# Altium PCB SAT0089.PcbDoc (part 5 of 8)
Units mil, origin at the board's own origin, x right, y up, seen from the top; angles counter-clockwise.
Board outline 4075 x 2715 mil, 6 copper layers (Top Layer, InternalPlane1, MidLayer1, Internal Plane 3, InternalPlane2, Bottom Layer), stack 67.4 mil thick; 538 components, 405 nets, 1716 pads, 1236 vias.
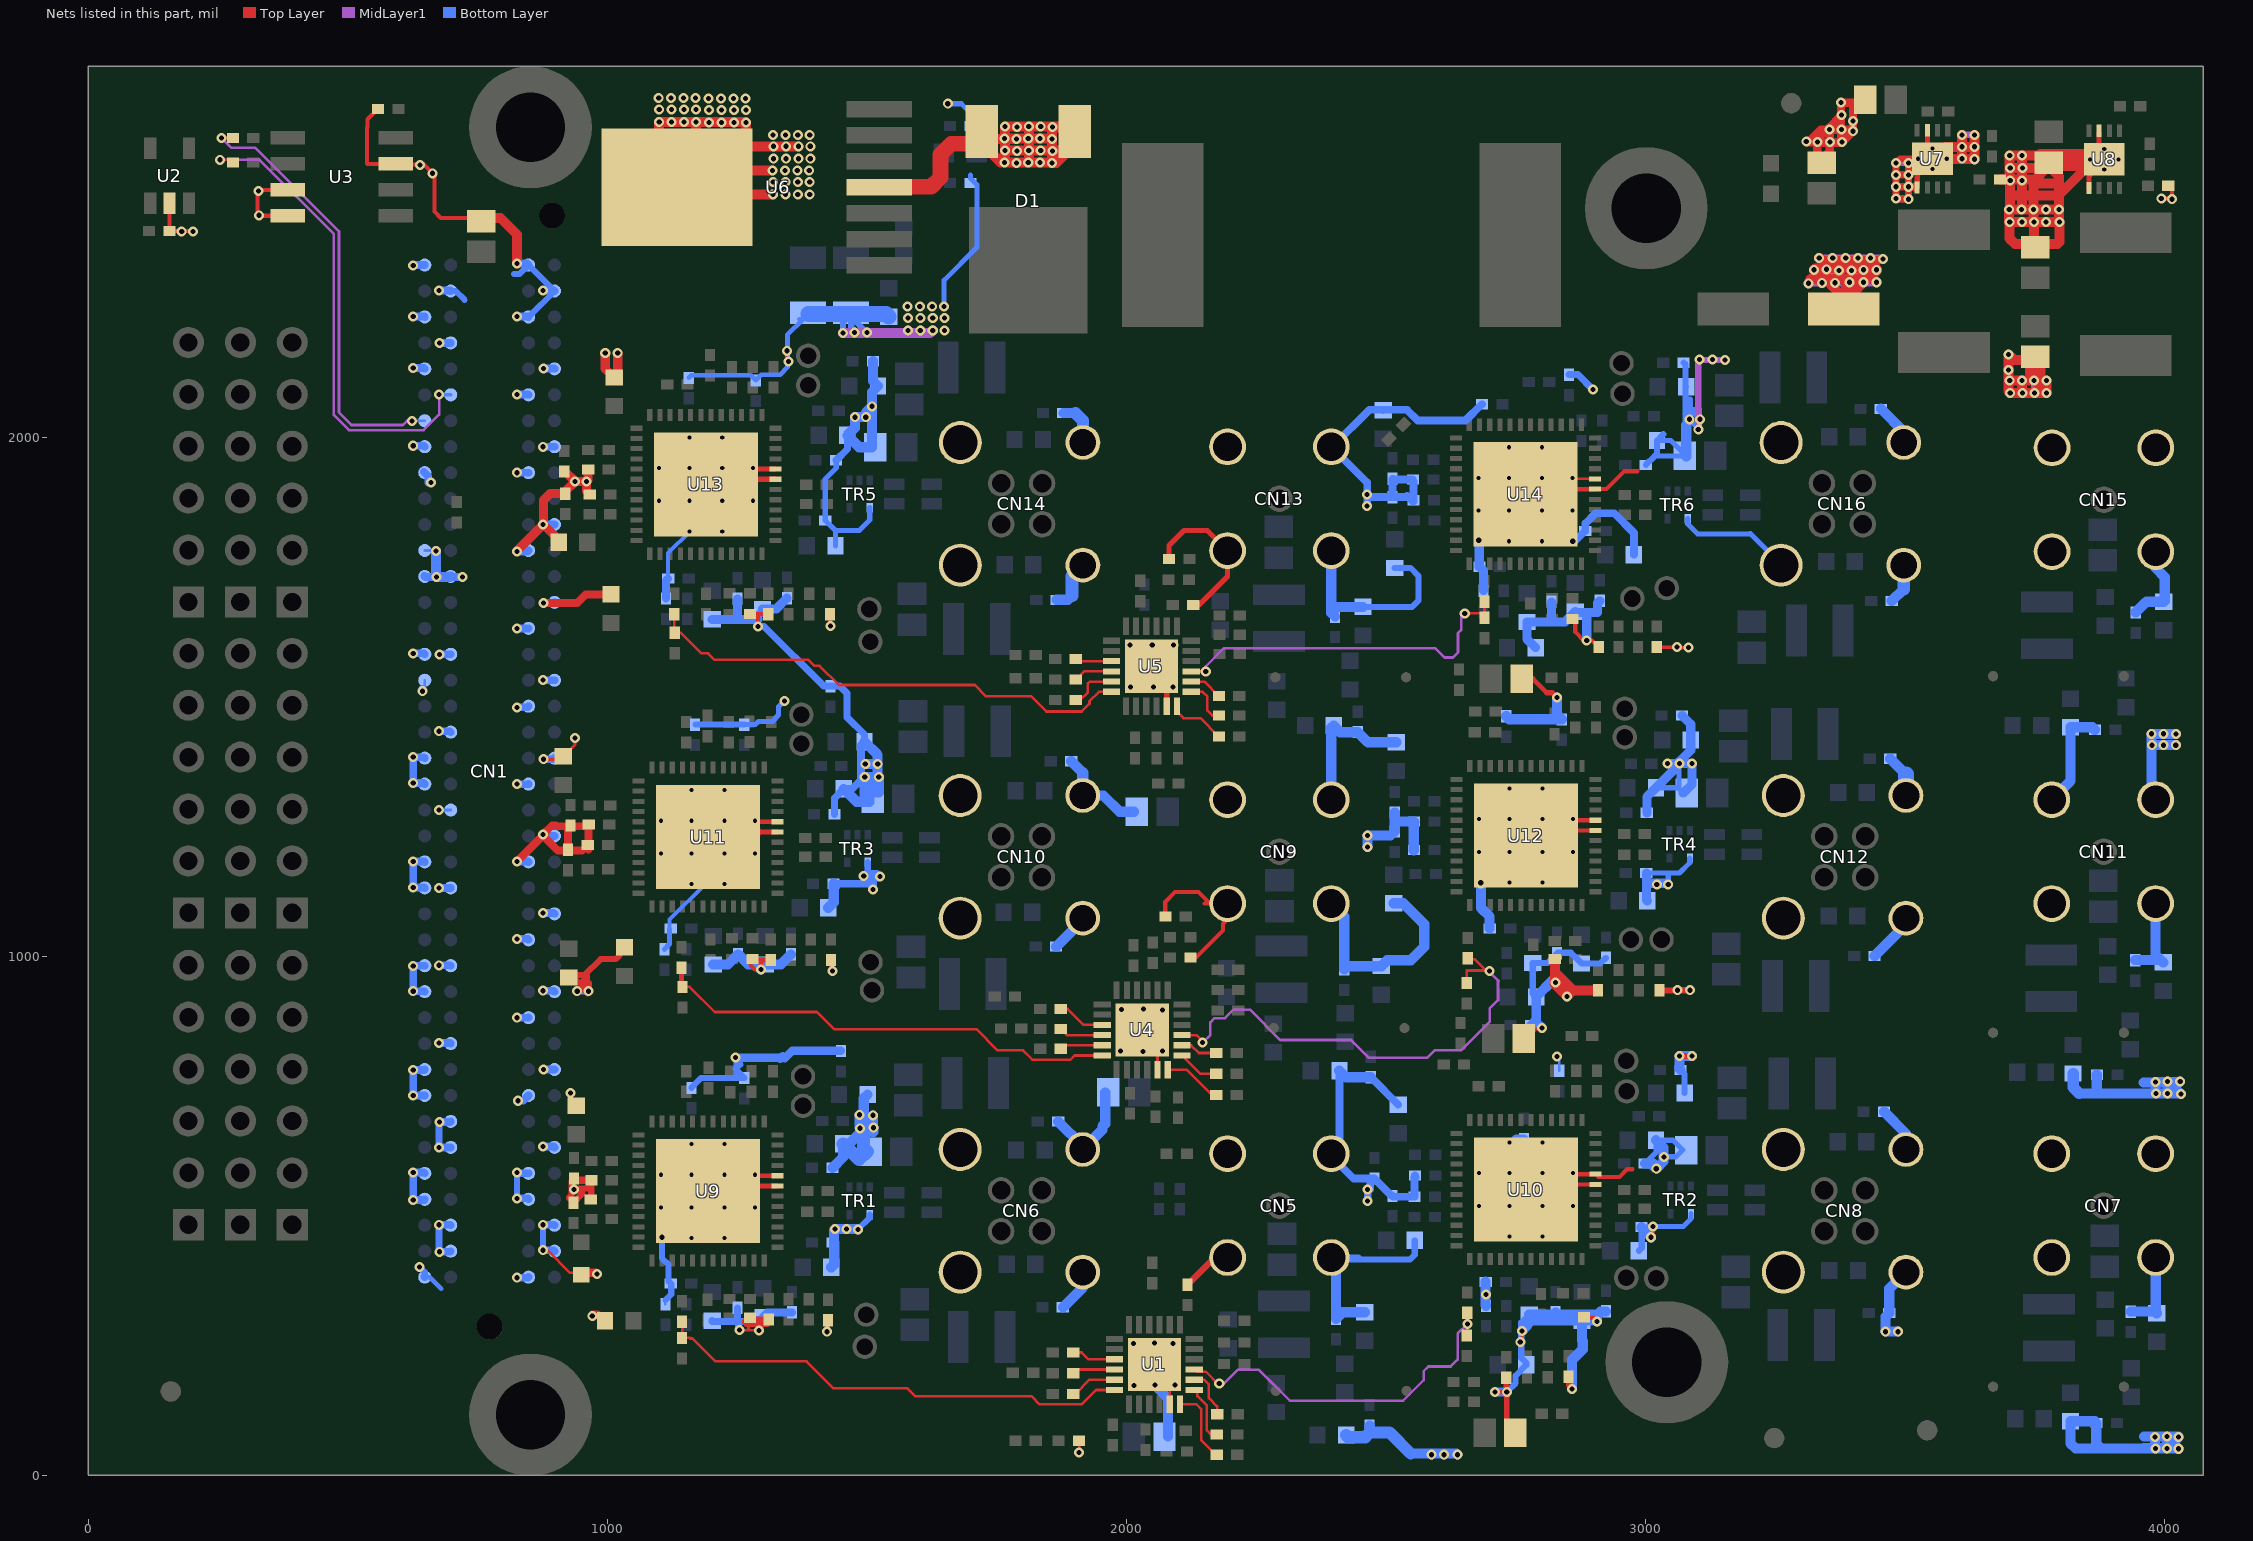
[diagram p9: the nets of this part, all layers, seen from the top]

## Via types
v1: diameter 19.29, hole 9.84, Top Layer to Bottom Layer, tented both sides, 1155 vias
v2: diameter 19.68, hole 7.87, Top Layer to Bottom Layer, tented both sides, 80 vias
v3: diameter 22, hole 10, Top Layer to Bottom Layer, tented both sides, 1 vias

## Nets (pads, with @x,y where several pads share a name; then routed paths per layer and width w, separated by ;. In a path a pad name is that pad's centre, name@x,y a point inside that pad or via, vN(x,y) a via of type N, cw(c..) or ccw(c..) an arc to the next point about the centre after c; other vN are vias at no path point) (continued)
DGND: C1.2 C2.1 C3.2 C4.2 C5.1 C6.1 C7.2 C8.2 C9.2 C11.2 C12.2 C13.2 C14.2 C15.2 C16.2 C17.2 C18.2 C19.2 C22.2 C27.2 C28.2 C29.2 C30.2 C31.2 C32.2 C33.2 C34.2 C35.2 C36.2 C37.2 C38.2 C39.2 C40.2 C41.2 C42.2 C43.2 C44.2 C45.2 C46.2 C47.2 C48.2 C49.2 C50.2 C51.2 C54.2 C59.2 C60.2 C61.2 C62.2 C63.2 C64.2 C65.2 C66.2 C67.2 C68.2 C69.2 C70.2 C71.2 C72.2 C73.2 C74.2 C75.2 C76.2 C77.2 C78.2 C79.2 C80.2 C81.2 C82.2 C83.2 C86.2 C91.2 C92.2 C93.2 C94.2 C95.2 C96.2 C97.2 C98.2 C99.2 C100.2 C101.2 C102.2 C103.2 C104.2 C105.2 C106.2 C107.2 C108.2 C109.2 C110.2 C111.2 C112.2 C113.2 C114.2 C115.2 C118.2 C123.2 C124.2 C125.2 C126.2 C127.2 C128.2 C129.2 C130.2 C131.2 C132.2 C133.2 C134.2 C135.2 C136.2 C137.2 C138.2 C139.2 C140.2 C141.2 C142.2 C143.2 C144.2 C145.2 C146.2 C147.2 C150.2 C155.2 C156.2 C157.2 C158.2 C159.2 C160.2 C161.2 C162.2 C163.2 C164.2 C165.2 C166.2 C167.2 C168.2 C169.2 C170.2 C171.2 C172.2 C173.2 C174.2 C175.2 C176.2 C177.2 C178.2 C179.2 C182.2 C186.2 C187.2 C188.2 C189.2 C190.2 C191.2 C192.2 C193.2 C194.2 C195.2 C196.2 C197.2 C198.2 C199.2 C200.2 C201.2 C202.2 C203.2 C204.2 C205.2 C206.2 C208.2 C209.2 C210.2 C211.2 C212.2 C213.2 CN1.1 CN1.4 CN1.5 CN1.8 CN1.9 CN1.12 CN1.13 CN1.16 CN1.17 CN1.20 CN1.21 CN1.24 CN1.25 CN1.28 CN1.29 CN1.32 CN1.33 CN1.36 CN1.38 CN1.40 CN1.42 CN1.43 CN1.46 CN1.47 CN1.50 CN1.53 CN1.56 CN1.59 CN1.62 CN1.65 CN1.68 CN1.77 CN1.79 CN1.81 CN1.84 CN1.85 CN1.88 CN1.91 CN1.94 CN1.97 CN1.100 CN1.103 CN1.106 CN1.109 CN1.112 CN1.115 CN1.118 CN1.120 CN1.122 CN1.123 CN1.126 CN1.129 CN1.132 CN1.135 CN1.138 CN1.141 CN1.144 CN1.147 CN1.150 CN1.153 CN1.156 CN1.159 CN5.2 CN5.3 CN5.4 CN5.5 CN6.5 CN6.6 CN6.7 CN6.8 CN7.2 CN7.3 CN7.4 CN7.5 CN8.5 CN8.6 CN8.7 CN8.8 CN9.2 CN9.3 CN9.4 CN9.5 CN10.5 CN10.6 CN10.7 CN10.8 CN11.2 CN11.3 CN11.4 CN11.5 CN12.5 CN12.6 CN12.7 CN12.8 CN13.2 CN13.3 CN13.4 CN13.5 CN14.5 CN14.6 CN14.7 CN14.8 CN15.2 CN15.3 CN15.4 CN15.5 CN16.5 CN16.6 CN16.7 CN16.8 D1.1 D1.3 R3.2 R8.2 R11.2 R13.1 R15.2 R16.2 R19.2 R21.2 R28.1 R29.1 R30.2 R38.2 R39.2 R55.1 R56.1 R57.2 R63.2 R64.2 R79.1 R80.1 R81.2 R87.2 R88.2 R103.1 R104.1 R105.2 R111.2 R112.2 R127.1 R128.1 R129.2 R135.2 R136.2 R151.1 R152.1 R153.2 R159.2 R160.2 TR1.4 TR2.4 TR3.4 TR4.4 TR5.4 TR6.4 U1.23 U1.25 U2.2 U3.3 U3.4 U3.7 U4.23 U4.25 U5.23 U5.25 U6.4 U6.8 U7.1 U7.7 U7.9 U8.1 U8.7 U8.9 U9.43 U9.44 U9.49 U10.43 U10.44 U10.49 U11.43 U11.44 U11.49 U12.43 U12.44 U12.49 U13.43 U13.44 U13.49 U14.43 U14.44 U14.49 | length 34902.5
  Top Layer w5: v1(876,434) 885,434 928.5,390.5 C34.2@950,390.5 ; v1(929,737) 929,723.5 C29.2@940,712.5 ; U9.49@1194,548 U9.49@1285,548 ; v1@1251,280 v1(1255,280) 1275,280 ; v1(1292,279) 1291,280 1275,280 ; R39.2@1310,299 1272,299 1272,283 1275,280 ; v1(1346,2167) 1346,2149 v1(1349,2146) ; v1(1909,44) R3.2@1909,67 ; U4.25@2030.55,858.35 U4.25@2032,856.9 ; v1(2032,817) U4.25@2032,856.9 ; U1.25@2054,214 2083.53,184.47 U1.23@2083.53,137.23 ; U4.23@2060.08,781.57 2060.08,828.82 U4.25@2032,856.9 ; U10.49@2736,462 U10.49@2808,462 ; U12.49@2740,1144 2740,1203 U12.49@2770,1233 2770,1188 U12.49@2750,1168 ; U14.49@2749,1825 2769,1845 2769,1890 U14.49@2769,1890.53 2769.53,1890.53 2790.53,1890.53 2800.37,1900.37 U14.49@2820.06,1920.06 ; U10.49@2750,486 U10.49@2770,506 ; v1(2759,257) 2762,260 v1(2762,278) ; U10.49@2770,551 U10.49@2770,506 ; C139.2@2772,842 2792,862 v1(2801,862) ; U14.49@2798,1919.53 2798.53,1920.06 U14.49@2820.06,1920.06 ; U10.49@2809,461 U10.49@2808,462 ; U14.49@2860,1895 U14.49@2865.37,1900.37 ; U14.49@2860,1960 U14.49@2820.06,1920.06 ; U14.44@2902.86,1920.06 2860,1920.06 U14.49@2820.06,1920.06 ; v1(3011,459) 3015,463 v1(3015,480) ; U10.49@2770,506 2770,500 U10.49@2808,462
  Top Layer w6: v1(877,1380) 909.5,1380 938,1408.5 v1(938,1421) ; C92.2@929,1252 C210.2@962,1252
  Top Layer w7: R159.2@3022,1596 v1(3061,1596) 3067,1596 3068,1595 v1(3083,1595)
  Top Layer w7.87: U13.49@1100,1820 U13.49@1189,1820 ; U11.49@1194,1230 U11.49@1203.84,1239.84 ; R30.2@1274,297 1274,296 R30.2@1275,296 ; U13.49@1277,1909 U13.49@1287.37,1919.37 ; U11.49@1290.84,1239.84 U11.49@1203.84,1239.84 ; v1(1292,279) v1@1293,278 ; 1296,296 v1@1296,285 ; R39.2@1307,296 v1@1296,285 ; U11.44@1327.86,1259.53 1223.53,1259.53 U11.49@1203.84,1239.84 ; v1(1423,277) 1425,279 R38.2@1425,299 ; R87.2@1431,993 1431,975 v1(1434,972) ; v1@3723.83,2497.17 v1(3726,2495) ; v1(3994,2460) 4014,2460 v1(4015,2459) 4015,2478 R21.2@4008,2485 ; v1@1293,278 v1@1296,281 ; v1@1293,278 1296,278 v1@1296,281 ; v1@1296,281 v1@1296,285
  Top Layer w8: U2.2@156.54,2452.83 U2.2@156.54,2450.87 156.54,2398.03 156.85,2397.72 v1@180,2397.72 ; v1(180,2397) v1@180,2397.72 ; v1(202,2397) 201.28,2397.72 v1@180,2397.72 ; v1(329,2428) 329.95,2427.05 v1@332.95,2427.05 ; U3.3@385.21,2477.05 329.05,2477.05 326,2474 326,2434 v1@332.95,2427.05 ; C4.2@558,2633 538,2613 538,2598 537,2597 537,2528 537.95,2527.05 593.21,2527.05 594.26,2526 647,2526 667,2506 667,2435 679,2423 C1.2@757,2423 ; U9.49@1203.84,557.84 1223.53,577.53 U9.44@1327.86,577.53 ; R129.2@1274.69,1660 1309,1660 1310,1659 1290,1659 v1(1290,1636) ; R81.2@1276,993 1276,983 1284,975 v1(1296,975) ; R135.2@1429,1659 1429,1638 v1(1430,1637) ; R8.2@2075,1077 2075,1105 2094,1124 2139,1124 CN9.3@2161,1102 ; C5.1@2120.5,997.5 2121,998 C5.1@2123.68,998 2134,998 2186,1050 2186,1063 2195,1072 CN9.3@2195,1102 ; 2151,1102 CN9.3@2161,1102 ; CN9.3@2200,1102 CN9.3@2195,1102 ; U14.49@2769,1890 2769.53,1890.53 U14.49@2778.84,1899.84 ; U10.49@2770,551 U10.49@2779.84,560.84 ; U12.49@2770,1233 U12.49@2779.84,1242.84 ; U14.49@2778.32,1899.84 U14.49@2778.84,1899.84 ; U14.49@2778.84,1900.37 2798,1919.53 2798.53,1919.53 2779.37,1900.37 U14.49@2778.84,1899.84 ; R153.2@2865,1645 2865,1625 2881,1609 v1(2887,1609) 2897,1609 R160.2@2910,1596 ; R57.2@2880,304 2900,304 v1(2907,297) ; U14.43@2902.86,1900.37 2925.37,1900.37 2960,1935 2985,1935 ; U10.43@2903.86,560.84 U10.49@2779.84,560.84 ; U12.43@2903.86,1242.84 U12.49@2779.84,1242.84 ; U12.44@2903.86,1262.53 2799.53,1262.53 U12.49@2779.84,1242.84 ; 2975,590 2965,590 2950,575 2909.39,575 U10.44@2903.86,580.53 2799.53,580.53 U10.49@2779.84,560.84 ; v1@332.95,2427.05 385.21,2427.05 385.17,2427 333,2427 v1@332.95,2427.05 ; CN9.3@2161,1102 CN9.3@2195,1102
  Top Layer w9: U14.49@2769,1890.53 2778.32,1899.84 2778.84,1900.37 2779.37,1900.37 2800.37,1900.37 2860,1900.37 2865.37,1900.37 U14.43@2902.86,1900.37
  Top Layer w9.84: U9.49@1194,548 1203.84,557.84 U9.43@1327.86,557.84 ; U13.49@1199.84,1919.37 1287.37,1919.37 U13.43@1323.86,1919.37 ; U13.49@1219.53,1939.06 U13.44@1323.86,1939.06 ; U11.49@1290.84,1239.84 U11.43@1327.86,1239.84 ; U12.49@2740,1144 2741,1143 U12.49@2809,1143 ; U14.49@2747,1963 U14.49@2810,1963 ; U14.49@2810,1962 U14.49@2810,1963 ; U14.49@2860,1895 2860,1900.37 2860,1920.06 2860,1960 2863,1963 U14.49@2810,1963 ; U7.1@3523.93,2481.43 U7.9@3523.93,2507.02 ; U7.9@3543.61,2546.39 U7.7@3543.61,2591.66 ; U8.1@3854.64,2477.49 3854.64,2503.08 U8.9@3874.56,2523 ; U8.9@3874.32,2542.45 U8.7@3874.32,2587.72
  Top Layer w10: U13.49@1199.84,1919.37 U13.49@1219.53,1939.06 ; R81.2@1276,993 1296,993 ; v1(1296,975) 1296,993 ; R88.2@1315,993 1296,993 ; v1(2050,1600) 2050,1560.87 U5.25@2048.27,1559.13 2077.8,1529.61 U5.23@2077.8,1482.36 ; R11.2@2082,1766 2082,1792 2111,1821 2155.97,1821 CN13.3@2195,1781.97 2195,1732 2140,1677 C6.1@2129,1677 ; v1(2710,161) v1(2733,161) ; R64.2@2732,188 2732,162 v1(2733,161) ; C75.2@2756,82 2756,97 2733,97 v1(2733,161) ; C202.2@2768,1535 2783,1535 2810,1508 2821,1508 v1(2830,1499) ; R63.2@2852,190 2852,174 v1(2859,167)
  Top Layer w11.81: C98.2@926,959.5 930,963.5 C98.2@930,964.5 ; 950,941 952,939 v1@961,930 ; 950,949.5 945,949.5 C98.2@930,964.5 ; 961,963 v1@961,930 ; v1(964,933) 962,931 962,929 v1@961,930 ; C42.2@995.5,298 C42.2@986.5,307 ; C106.2@1023.5,1017.5 1033,1017.5 1033,1012 1016,995 987,995 956.5,964.5 C98.2@930,964.5 ; U13.49@1190,1909.53 U13.49@1199.84,1919.37 ; U7.9@3523.93,2507.02 3553.46,2536.54 U7.9@3543.61,2546.39 ; C42.2@986.5,307 981.5,312 971,312 v1(971,307) C42.2@986.5,307
  Top Layer w12: C28.2@936,570 936,572 931,567 v1@931,551 ; v1(942,933) 946,933 v1@950,937 ; 952,939 v1@950,937 ; 959.5,959 950,949.5 950,941 v1@950,937 ; v1(964,933) 964,949 ; C31.2@969,532 969,553 ; C208.2@969,569 969,553 ; C2.1@2118,368 2170,420 CN5.3@2195,420 ; R111.2@3027.02,934.37 3061.37,934.37 v1(3062,935) v1(3086,935) ; v1(3066,808) v1(3090,808) ; v1@931,551 931,540 926,535 935,526 952,543 946,549 ; v1@931,551 v1(936,551) ; v1(936,551) 944,551 946,553 ; v1(936,551) 934,549 946,549 ; 946,549 948,551 946,553 ; 946,553 969,553
  Top Layer w13.78: U1.25@2054,214 2054,175 v1(2055,174) ; v1(3507,2529) v1(3507,2506) ; 3518,2481 3516,2483 v1(3507,2483) ; U7.9@3553.46,2536.54 3490.54,2536.54 v1(3483,2529) v1(3483,2506) ; v1(3483,2483) v1(3507,2483) ; v1(3483,2483) v1(3483,2506) ; v1(3483,2483) v1(3483,2460) 3506,2460 v1(3507,2459) v1(3507,2483) ; v1(3483,2506) v1(3507,2506) ; v1(3507,2483) v1(3507,2506)
  Top Layer w15: v1(826,1183) v1@876,1233 ; C97.2@924,1206 924,1247 C92.2@928,1251 ; C92.2@929,1252 C92.2@928,1251 ; C28.2@936,572 939,569 C208.2@969,569 ; U11.49@1284,1233 U11.49@1290.84,1239.84 ; v1@876,1233 v1(876,1235) 894,1253 900,1253 902,1251 C92.2@928,1251 ; v1@876,1233 905,1204 951,1204 C96.2@962,1215 ; C92.2@928,1251 961,1251 962,1252 964,1254 C96.2@964,1213 ; C96.2@962,1215 C96.2@964,1213 ; C96.2@962,1215 962,1208 964,1206 C96.2@964,1213
  Top Layer w15.75: v1(877,1681) 942,1681 958.5,1697.5 973.5,1697.5
  Top Layer w16: C34.2@950,390.5 977.5,390.5 v1(980,388) ; 973.5,1697.5 C170.2@1007,1697.5 ; v1(3400,2590) 3400,2589 v1@3379,2568 ; C14.2@3417.06,2650.72 3411.35,2645 3397,2645 ; v1@3314,2569 v1@3331,2569 ; v1@3314,2569 v1@3315,2570 ; v1@3314,2569 3311,2569 v1(3310,2570) v1@3315,2570 ; v1@3315,2570 3338,2593 v1@3350,2593 ; v1@3331,2569 3331,2535.16 3339.16,2535.16 3351.32,2547.32 3355,2547.32 v1@3355,2568 ; v1@3331,2569 v1(3332,2569) ; v1(3332,2569) 3332,2575 v1@3350,2593 ; v1(3332,2569) 3333,2568 v1@3355,2568 ; v1@3350,2593 v1@3352.5,2595.5 ; v1@3350,2593 v1(3355,2593) ; v1@3352.5,2595.5 v1@3377,2620 ; v1@3352.5,2595.5 v1(3355,2593) ; v1@3355,2568 v1@3355,2569 ; v1@3355,2568 v1@3356,2568 ; v1@3355,2569 v1(3355,2593) ; v1@3355,2569 v1(3356,2569) ; v1(3355,2593) v1@3377,2593 ; v1@3356,2568 v1@3357,2568 ; v1@3356,2568 v1(3356,2569) ; v1(3356,2569) v1@3357,2568 ; v1@3357,2568 v1@3379,2568 ; v1@3377,2593 3377,2571 v1(3379,2569) v1@3379,2568 ; v1@3377,2593 v1@3377,2620 ; v1@3377,2593 v1(3378,2593) 3399,2593 3400,2594 v1(3400,2610) 3400,2642 3397,2645 ; v1@3377,2620 v1@3377,2621 ; v1@3377,2620 v1(3378,2621) v1@3377,2621 ; v1@3377,2621 v1(3377,2645) 3397,2645
  Top Layer w17.72: v1(826,1780) 826,1782 v1(876,1832) ; C162.2@911.5,1798 877.5,1832 v1(876,1832) ; C156.2@917,1934 919,1934 v1(938,1915) ; C155.2@963,1938 963,1918 v1(960,1915) ; C160.2@967,1890 960,1897 v1(960,1915) ; v1(996,2163) 996,2132.5 1013,2115.5 1020,2122.5 v1(1020,2163) ; v1(876,1832) 877,1833 877,1879 890,1892 919,1892 919,1896 v1(938,1915) ; v1(938,1915) v1(960,1915)
  Top Layer w19.29: C1.2@757,2423 794,2423 826,2391 v1(826,2335) ; v1(1196,2607) v1@1196,2608 ; v1(1220,2607) v1@1220,2608 ; v1(1244,2607) v1@1244,2608 ; v1(1318,2514) U6.8@1209.81,2514 ; v1(1319,2468) 1193.81,2468 1178.81,2483 U6.8@1209.81,2514 ; v1(1368,2561) v1(1344,2561) v1(1320,2561) U6.8@1256.81,2561 ; v1(1788,2529) v1@1788,2530 ; v1(1789,2552) v1@1789,2553 ; v1(1789,2598) v1@1789,2599 ; R105.2@2826,995 2826,970 ; 2837,940 2834.5,937.5 ; R112.2@2908.91,934.37 2860.37,934.37 ; v1(3314,2297) v1@3317.76,2300.76 ; v1(3325,2323) v1@3326.13,2324.13 ; v1(3335,2346) 3340.92,2340.08 v1@3361.89,2340.08 ; v1(3349,2324) v1@3350.08,2325.08 ; v1(3361,2346) 3361.89,2345.11 v1@3361.89,2340.08 ; v1(3386,2346) 3385,2345 v1@3385,2340.08 ; C11.2@3386.46,2265 3358.46,2292.99 v1@3358.46,2298.46 ; v1(3397,2322) 3397.68,2322.68 v1@3397.68,2325.08 ; v1(3410,2346) 3407.68,2343.68 v1@3407.68,2340.08 ; v1(3434,2346) 3430,2342 v1@3430,2340.08 ; 3444.92,2340.08 v1@3430,2340.08 ; v1(3445,2299) v1@3439,2305 ; v1(3610,2583) v1(3610,2560) ; v1(3634,2583) v1(3634,2560) ; R19.2@3683.69,2497.17 v1@3702,2497.17 ; 3751,2125 v1@3751,2110 ; C13.2@3751,2149 3711,2149 v1(3700,2160) v1(3700,2130) v1@3700,2110 ; U8.9@3863.77,2553 3872.68,2544.09 3874.32,2542.45 3882.52,2534.25 U8.9@3884.17,2532.61 ; v1(1171,2608) v1@1196,2608 ; v1(1171,2608) 1171,2490.81 1100,2561.81 v1(1100,2608) v1(1124,2608) v1(1148,2608) v1(1171,2608) ; v1@1196,2608 v1@1220,2608 ; U6.8@1209.81,2514 U6.8@1256.81,2561 ; v1@1220,2608 v1@1244,2608 ; v1@1244,2608 1266,2608 v1(1267,2607) 1267,2571.19 U6.8@1256.81,2561 ; v1(1765,2530) v1@1788,2530 ; v1(1765,2530) 1757.91,2530 1721.89,2566.02 1730.87,2575 v1@1765,2575 ; v1(1765,2530) 1766,2531 v1(1766,2553) ; v1@1765,2575 v1@1766,2575 ; v1@1765,2575 v1(1765,2576) v1@1766,2576 ; v1(1766,2553) v1@1789,2553 ; v1(1766,2553) v1@1766,2575 ; v1@1766,2575 v1@1766,2576 ; v1@1766,2575 v1(1788,2575) v1@1788,2576 ; v1@1766,2576 v1(1766,2599) v1@1789,2599 ; v1@1766,2576 v1@1788,2576 ; v1@1788,2530 v1(1811,2530) ; v1@1788,2576 v1(1811,2576) v1@1812,2576 ; v1@1789,2553 v1(1812,2553) ; v1@1789,2599 v1(1812,2599) ; v1(1811,2530) v1(1834,2530) 1856,2530 v1(1857,2529) ; v1(1811,2530) 1812,2531 v1(1812,2553) ; v1(1812,2553) v1@1812,2576 ; v1(1812,2553) v1(1835,2553) v1@1857,2553 ; v1@1812,2576 v1(1812,2599) ; v1@1812,2576 v1(1834,2576) 1856,2576 v1(1857,2575) ; v1(1812,2599) v1(1835,2599) v1@1858,2599 ; v1(1857,2529) v1@1857,2552 ; v1(1857,2529) 1865.18,2529 D1.1@1889.18,2553 ; v1@1857,2552 v1@1857,2553 ; v1@1857,2552 v1(1858,2552) v1@1858,2553 ; v1@1857,2553 v1@1858,2553 ; v1@1857,2553 v1(1857,2575) ; v1(1857,2575) 1857,2597 v1(1858,2598) v1@1858,2599 ; v1@1858,2553 D1.1@1889.18,2553 ; v1@1858,2599 1869.23,2599 1902.2,2566.02 D1.1@1889.18,2553 ; 2826,970 2860.37,935.63 2860.37,934.37 ; 2826,970 2826,951 v1(2827,950) 2825,948 2825,947 2834.5,937.5 ; 2834.5,937.5 v1(2849,923) 2860.37,934.37 ; v1@3317.76,2300.76 3322,2305 ; v1@3317.76,2300.76 3317.76,2305 3322,2305 ; 3322,2305 3335,2305 3335,2303 v1(3340,2298) v1@3345,2303 ; v1@3326.13,2324.13 3331.85,2324.13 v1@3331.85,2325.08 ; v1@3326.13,2324.13 3327.08,2325.08 v1@3331.85,2325.08 ; v1@3331.85,2325.08 v1@3350.08,2325.08 ; v1@3331.85,2325.08 3340.96,2315.96 3345.96,2310.96 ; v1@3345,2303 3345.96,2303.96 v1@3345.96,2305 ; v1@3345,2303 3345,2305 v1@3345.96,2305 ; v1@3345.96,2305 3351.93,2305 ; v1@3345.96,2305 3345.96,2310.96 ; 3345.96,2310.96 3349.46,2307.46 3351.93,2305 ; v1@3350.08,2325.08 v1@3375,2325.08 ; 3351.93,2305 v1@3360,2305 ; 3351.93,2305 v1@3358.46,2298.46 ; v1@3358.46,2298.46 v1@3364.54,2298.46 ; v1@3360,2305 3365,2305 v1(3365,2298) ; v1@3360,2305 3360,2303 v1@3364.54,2298.46 ; v1@3361.89,2340.08 v1@3385,2340.08 ; v1@3364.54,2298.46 v1(3365,2298) ; v1(3365,2298) v1@3370,2303 ; v1@3370,2303 3372,2305 ; v1@3370,2303 3370,2305 3372,2305 ; 3372,2305 v1@3387.01,2305 ; 3372,2305 3375,2308 3375,2320 v1(3373,2322) 3375,2324 v1@3375,2325.08 ; v1@3375,2325.08 v1@3397.68,2325.08 ; v1@3385,2340.08 v1@3407.68,2340.08 ; v1@3387.01,2305 3414,2305 v1@3415,2304 ; v1@3387.01,2305 3387.01,2299.99 3392.01,2299.99 v1(3393,2299) 3392.01,2298.01 3387.01,2298.01 3387.01,2265.55 3410,2288.54 3410,2289 v1(3420,2299) v1@3415,2304 ; v1@3397.68,2325.08 v1@3420,2325.08 ; v1@3407.68,2340.08 v1@3430,2340.08 ; v1@3415,2304 v1@3415,2305 ; v1@3415,2305 v1@3439,2305 ; v1@3415,2305 3420,2310 v1(3420,2323) v1@3420,2325.08 ; v1@3420,2325.08 3444.92,2325.08 v1@3444.92,2322.92 ; v1@3439,2305 3435,2309 3435,2315 3440,2315 3440,2318 v1@3444.92,2322.92 ; v1@3444.92,2322.92 v1(3445,2323) 3445,2320.16 3444.92,2320.08 v1@3444.92,2322.92 ; v1@3610,2536.54 3633.46,2536.54 v1(3634,2536) v1(3634,2560) ; v1@3610,2536.54 3553.46,2536.54 3576.91,2560 v1(3610,2560) ; v1@3610,2536.54 v1(3610,2537) v1(3610,2560) ; v1(3610,2560) v1(3634,2560) ; v1@3700,2110 3700,2089 v1(3703,2086) v1(3727,2086) ; v1@3700,2110 v1(3702,2110) v1(3726,2110) ; v1(3701,2439) 3703,2441 3703,2466 ; v1(3701,2439) 3701,2416 v1(3702,2415) ; v1(3701,2439) v1(3725,2439) ; v1(3702,2415) 3702,2383 3712,2373 C12.2@3751,2373 ; v1(3702,2415) v1(3726,2415) v1(3749,2415) ; v1@3702,2497.17 v1@3703,2497.17 ; v1@3702,2497.17 v1@3702,2519 ; v1@3702,2497.17 3702,2496 v1(3703,2495) ; v1@3702,2519 v1(3702,2543) v1(3726,2543) ; v1@3702,2519 v1(3703,2519) v1@3726,2519 ; 3703,2466 3726,2466 ; 3703,2466 v1(3703,2495) ; v1(3703,2495) v1@3703,2497.17 ; v1@3703,2497.17 3723.83,2497.17 v1@3726,2497.17 ; v1(3725,2439) 3726,2440 3726,2466 ; v1(3725,2439) v1(3748,2439) ; v1(3726,2110) 3726,2087 v1(3727,2086) ; v1(3726,2110) v1(3749,2110) v1@3751,2110 ; 3726,2466 v1(3726,2495) v1@3726,2497.17 ; 3726,2466 3748,2466 ; v1@3726,2497.17 3751.17,2497.17 ; v1@3726,2497.17 v1@3726,2519 ; v1@3726,2519 v1(3726,2543) ; v1@3726,2519 v1(3727,2519) C15.2@3773,2519 ; v1(3726,2543) C15.2@3757,2543 ; v1(3727,2086) v1(3750,2086) v1(3773,2086) ; v1(3748,2439) 3748,2466 ; v1(3748,2439) 3748,2416 v1(3749,2415) ; v1(3748,2439) v1(3772,2439) v1(3797,2439) ; 3748,2466 3748,2487 ; 3748,2466 3796,2466 3797,2467 ; 3748,2487 3748,2494 3751.17,2497.17 ; 3748,2487 3750,2489 3797,2489 ; v1(3749,2415) 3749,2375 C12.2@3751,2373 ; v1(3749,2415) v1(3772,2415) v1(3798,2415) ; v1@3751,2110 3751,2108 v1(3773,2086) ; v1@3751,2110 v1(3773,2110) v1(3773,2086) ; C12.2@3751,2373 3794,2373 3798,2377 v1(3798,2415) ; 3751.17,2497.17 C15.2@3773,2519 ; C15.2@3757,2543 C15.2@3777,2523 ; C15.2@3757,2543 3760,2546 3844,2546 U8.9@3857.39,2532.61 ; C15.2@3773,2519 C15.2@3777,2523 ; C15.2@3777,2523 U8.9@3853,2523 ; C15.2@3777,2523 3786.61,2532.61 U8.9@3857.39,2532.61 ; C15.2@3777,2523 3797,2503 3797,2489 ; v1(3797,2439) 3797,2467 ; v1(3797,2439) 3797,2416 v1(3798,2415) ; 3797,2467 U8.9@3853,2523 ; 3797,2467 3797,2489 ; U8.9@3853,2523 3874.56,2523 U8.9@3884.17,2532.61 ; U8.9@3853,2523 U8.9@3862.61,2532.61 ; U8.9@3857.39,2532.61 U8.9@3862.61,2532.61 ; U8.9@3862.61,2532.61 U8.9@3884.17,2532.61
  Top Layer w19.68: R30.2@1269,296 1272,299 1274,297 1275,296 1296,296 1307,296 1310,299 R39.2@1311,300
  Top Layer w20: U6.8@1171,2490.81 U6.8@1178.81,2483 ; C11.2@3386.46,2265 C11.2@3387.01,2265.55 ; 3444.92,2340.08 3445,2340
  Top Layer w30: U6.4@1542,2483 1624,2483 1642,2501 1642,2545 1663.02,2566.02 D1.3@1721.89,2566.02
  Top Layer w39: 3751,2125 C13.2@3751,2149
  MidLayer1 w12: v1(3102,2015) v1@3102,2035 ; v1(3105,2035) v1@3102,2035 ; v1(3129.02,2150.32) v1@3129.02,2149.33 ; v1(3153.23,2149.33) v1@3129.02,2149.33 ; v1(3310,2570) v1@3332,2570 ; v1(3314,2297) v1@3340,2297 ; v1(3325,2323) v1@3349,2323 ; v1(3332,2569) v1@3332,2570 ; v1(3335,2346) v1(3361,2346) ; v1(3349,2324) v1@3349,2323 ; v1(3365,2298) v1@3365,2297 ; v1(3373,2322) v1@3373,2323 ; v1(3377,2645) v1@3377,2621 ; v1(3378,2621) v1@3377,2621 ; v1(3379,2569) v1@3378,2570 ; v1(3393,2299) v1@3393,2297 ; v1(3397,2322) v1@3397,2323 ; v1(3400,2610) v1(3400,2590) 3397,2593 v1(3378,2593) v1@3377,2593 ; v1(3445,2299) 3443,2297 v1@3420,2297 ; v1(3445,2323) v1(3420,2323) 3410,2323 ; v1(3458,2344) 3456,2346 v1(3434,2346) v1(3410,2346) ; v1(3700,2160) v1(3700,2130) v1@3700,2110 ; v1(3703,2519) v1@3702,2519 ; v1(3727,2519) v1@3726,2519 ; v1@3102,2035 3102,2147.83 v1(3104.17,2150) 3104.84,2149.33 v1@3129.02,2149.33 ; v1@3332,2570 v1@3355,2570 ; v1@3340,2297 v1@3365,2297 ; v1@3340,2297 v1(3340,2298) 3361,2319 3361,2323 ; v1@3349,2323 3361,2323 ; v1@3355,2570 v1@3356,2570 ; v1@3355,2570 v1(3356,2569) v1@3356,2570 ; v1@3355,2570 v1(3355,2593) v1@3377,2593 ; v1@3356,2570 v1@3378,2570 ; 3361,2323 v1(3361,2346) ; 3361,2323 v1@3373,2323 ; v1(3361,2346) v1(3386,2346) v1(3410,2346) ; v1@3365,2297 v1@3393,2297 ; v1@3373,2323 v1@3397,2323 ; v1@3377,2593 v1@3377,2621 ; v1@3377,2593 3377,2571 v1@3378,2570 ; v1@3393,2297 v1@3420,2297 ; v1@3397,2323 3410,2323 ; 3410,2323 v1(3410,2346) ; 3410,2323 3410,2309 v1(3420,2299) v1@3420,2297 ; v1(3483,2483) v1(3507,2483) ; v1(3483,2483) v1(3483,2506) ; v1(3483,2483) v1(3483,2460) 3484,2459 v1(3507,2459) v1(3507,2483) ; v1(3483,2506) v1(3507,2506) ; v1(3483,2506) v1(3483,2529) v1(3507,2529) v1(3507,2506) ; v1(3507,2483) v1(3507,2506) ; v1@3700,2110 3700,2089 v1(3703,2086) v1(3727,2086) ; v1@3700,2110 v1(3702,2110) v1(3726,2110) ; v1@3702,2519 v1(3702,2543) v1(3726,2543) v1@3726,2519 ; v1@3702,2519 3702,2496 v1(3703,2495) v1(3726,2495) v1@3726,2519 ; v1(3726,2110) 3726,2087 v1(3727,2086) ; v1(3726,2110) v1(3749,2110) ; v1(3727,2086) v1(3750,2086) ; v1(3748,2439) 3748,2416 v1(3749,2415) ; v1(3748,2439) v1(3772,2439) v1(3797,2439) 3797,2416 v1(3798,2415) v1(3772,2415) v1(3749,2415) ; v1(3748,2439) v1(3725,2439) v1(3701,2439) 3701,2416 v1(3702,2415) v1(3726,2415) v1(3749,2415) ; v1(3749,2110) 3749,2087 v1(3750,2086) ; v1(3749,2110) v1(3773,2110) v1(3773,2086) v1(3750,2086) ; v1(3610,2537) 3633,2537 v1(3634,2536) v1(3634,2560) v1(3634,2583) v1(3610,2583) v1(3610,2560) v1(3610,2537)
  MidLayer1 w19.29: v1(1454,2201) v1@1476,2201 ; v1(1476,2202) v1@1476,2201 ; v1(1500,2202) v1@1500,2201 ; v1(1579,2206) v1@1579,2201 ; v1(1603,2206) v1@1603,2201 ; v1(1627,2206) 1622,2201 v1@1603,2201 ; v1@1476,2201 v1@1500,2201 ; v1@1500,2201 v1@1579,2201 ; v1@1579,2201 v1@1603,2201
  Bottom Layer w5: v1(644,1511) 648.27,1515.27 CN1.24@648.27,1532.17 ; CN1.29@648.27,1782.17 668.83,1782.17 v1(670,1781) ; v1(676,1282) 676.17,1282.17 CN1.59@698.27,1282.17 ; C41.2@1112,330 C41.2@1112,338 ; C32.2@1122,370 C32.2@1123,369 ; C94.2@1169,1446 C94.2@1170,1447 ; v1(2830,807) 2834,803 C209.2@2834,780 ; 2896.5,298.5 v1@2905.5,298.5 ; v1@2907,299 C68.2@2922,314 ; 3079,2024 3085,2030 v1(3085,2035)
  Bottom Layer w7.87: C159.2@1117,1728 1117,1777 v2@1160,1820
  Bottom Layer w8: C95.2@1120,1053 1120,1071 1189,1140 v2@1225.46,1140 ; 1246,766 1247,767 1247,783 1247,801 v1@1247,803
  Bottom Layer w9: CN1.1@648.27,382.17 657.83,382.17 680,360 ; C158.2@1157,2115 1162,2120 1276,2120 1286,2110 1297,2121 1333,2121 1347,2135 v1@1347,2148 ; v1(1346,2167) v1@1347,2167 ; v1(1349,2146) v1@1347,2148 ; C7.2@1370,2228 C7.2@1377.36,2228 ; C7.2@1387.25,2237.89 C7.2@1377.36,2228 ; v1@1347,2148 v1@1347,2167 ; v1@1347,2167 1347,2197.64 C7.2@1377.36,2228
  Bottom Layer w9.84: v1(1649,2252) 1649,2303 1712,2366 1712,2487 1700,2499 1700,2506 ; v1(1656,2643) 1682,2643 1700,2625 1700,2586 ; 2747,1963 2809,1963 2810,1962
  Bottom Layer w10: C105.2@1110,1014 1120,1024 C95.2@1120,1053 ; C91.2@1264,1447 1285,1447 1291,1453 1318,1453 1330,1465 1330,1481 v1(1341,1492) ; v1(1290,1636) 1290,1649 1290,1660.5 C168.2@1299,1669.5 ; C167.2@1439.5,1791 1439.5,1820.5 ; C175.2@1441,1956 1441,1941 1420,1920 1420,1840 1439.5,1820.5 ; TR5.4@1505.68,1864.43 1505.68,1840.68 1485.5,1820.5 1439.5,1820.5 ; v1(2759,257) 2761,259 2762,260 v1(2762,278) ; C67.2@2993,479 3014,479 v1(3015,480) 3073,480 3087.68,494.68 TR2.4@3087.68,504.43 ; C79.2@2999,601 3020.5,622.5 3020.5,646 C76.2@3020.56,646 3053,646 3072,627 3059,614 v1(3036,614) ; C130.2@3002,1161 3042,1161 ; 3018,1964 3079,1964 3049,1994 C203.2@3022.56,1994 C203.2@3022.5,1994 ; C128.2@3020.5,1325 C128.2@3020.56,1325 3063,1325 C118.2@3065,1323 ; v1(3044,1139) 3044,1159 3042,1161 ; v1@3065,1375 3065,1372 C118.2@3065,1323 ; C118.2@3073,1315 C118.2@3065,1323 ; 3077.5,2054 3086.5,2054 ; 3077.5,2073.5 3086.5,2073.5 3086.5,2054 ; TR6.4@3081.68,1843.43 3081.68,1833.32 3101,1814 3201,1814 3202,1815 3261.5,1755.5 CN16.5@3261.5,1753.99 ; TR4.4@3085.68,1189.43 3085.68,1180.68 3066,1161 3042,1161 ; v1(3102,2015) v1@3104,2015 ; 3086.5,2054 3086.5,2032.5 v1@3104,2015 ; 3086.5,2054 3104,2054 ; v1@3104,2015 v1@3104,2035 ; v1@3104,2035 v1@3104,2036 ; v1@3104,2035 v1(3105,2035) v1@3104,2036 ; v1@3104,2036 3104,2054 ; v1@3104,2036 3097,2043 3097,2047 3104,2054
  Bottom Layer w11.8: v1(638,402) 648.27,391.73 CN1.1@648.27,382.17
  Bottom Layer w11.81: CN1.79@698.27,2282.17 707.83,2282.17 725,2265 ; 820,2315 831.1,2315 CN1.120@848.27,2332.17 CN1.159@897.43,2283 ; v1(826,534) v1(826,584) ; CN1.118@848.27,2232.17 CN1.159@898.27,2282.17 ; v1(876,434) v1(876,483) ; v1(942,933) v1(964,933) ; v1(1105,459) 1105,419 1118,406 1118,374 C32.2@1122,370 ; C30.2@1162,747 1181,766 1246,766 1264,766 1247,783 1256,792 1247,801 1246,802 1247,803 v1(1247,805) ; 1283,638 1283,550 1285,548 ; v1(1483,474) 1505.68,496.68 TR1.4@1505.68,502.43 ; v1(1494,1155) 1501,1148 1501,1144 ; 1501.68,1144.68 1501.68,1160 TR3.4@1501.68,1181.43 ; C147.2@2456,1673.5 2550.5,1673.5 2563,1686 2563,1733 2547.5,1748.5 C193.2@2517,1748.5 ; C69.2@2827,314 2904,314 ; v1@2904,300 2904,306 2904,314 ; C68.2@2924,316 2922,314 2912,314 2904,314 ; C8.2@1469.93,2232.07 1469.93,2208.07 v1(1476,2202) v1@1476,2201 ; C8.2@1469.93,2232.07 v1(1500,2202) 1499,2201 v1@1476,2201 ; C8.2@1469.93,2232.07 1469.93,2237.89 1454,2221.96 v1(1454,2201) v1@1476,2201
  Bottom Layer w12: C41.2@1112,338 1123,349 C32.2@1123,369 ; C94.2@1170,1447 C91.2@1264,1447 ; CN5.4@2395,420 CN5.4@2400,420 ; C66.2@2555.5,453 2555.5,425.5 2546,416 2451,416 ; v1(2733,161) 2750,178 2750,192.5 2770.5,213 2770.5,217 2761,226.5 v1@2761,257 ; v1(2759,257) v1@2761,257 ; v1(2762,278) v1@2761,278 ; C71.2@2776,309.5 2761,294.5 v1@2761,278 ; C137.2@2789.5,922 2783,928.5 C125.2@2783,987.44 2783,987.5 2811.5,987.5 2831,1007 2856.5,1007 2877,986.5 2913.5,986.5 C123.2@2924,997 ; C72.2@2987.5,433 2993,438.5 C67.2@2993,477 ; C206.2@3001,1947 3018,1964 3022.5,1968.5 3022.5,1994 C203.2@3034.5,2006 ; C77.2@3068,781 3075.5,773.5 C78.2@3075.5,737 ; C204.2@3074,2144 3077.5,2140.5 3077.5,2099 3078.5,2098 3077.5,2097 3077.5,2073.5 3077.5,2054 3077.5,2042.5 ; 3077.5,2027.5 3077.5,2042.5 ; v1(3085,2035) 3077.5,2042.5 ; CN5.4@2400,420 2447,420 2451,416 ; CN5.4@2400,420 2404,416 2451,416 ; v1@2761,257 2761,259 v1@2761,278
  Bottom Layer w13.78: v1(626,531) v1(626,584) ; v1(626,732) v1(626,781) ; v1(626,933) v1(626,982) ; v1(626,1133) v1(626,1183) ; v1(626,1334) v1(626,1384) ; v1(676,483) 676,432 v1(677,431) ; v1(676,632) 676,680 v1(677,681) ; C40.2@1202,298.5 C40.2@1202,298.44 1202,296.5 1253,296.5 ; 1250,297.5 1251,297.5 ; C35.2@1251,323 1251,297.5 ; v1(1255,280) 1253,282 1253,296.5 ; v1(1290,1636) 1302,1636 1417,1521 1448,1521 1462,1507 1462,1461 1495.5,1427.5 C110.2@1495.5,1414 ; C39.2@1300,305.5 C39.2@1300,305.44 1300,296.5 1253,296.5 ; C100.2@1436,1140 1497,1140 ; C111.2@1438,1274 1438,1305.5 C108.2@1455.5,1323 ; C175.2@1441,1956 1462.5,1977.5 C172.2@1462.5,2004 ; v1(1494,1155) 1499,1160 1501.68,1160 1519,1160 v1(1525,1154) 1522,1151 1513,1151 1513,1130 v1(1512,1129) 1511,1130 1511,1140 1497,1140 ; 1501.68,1144.68 1501,1144 1497,1140 ; C186.2@2853,2121 2870,2121 v1(2899,2092) ; 1251,297.5 1252,297.5 1253,296.5
  Bottom Layer w15: v1(626,531) 647.1,531 CN1.4@648.27,532.17 ; v1(626,584) 646.43,584 CN1.5@648.27,582.17 ; v1(626,732) 648.1,732 CN1.8@648.27,732.17 ; v1(626,781) 647.1,781 CN1.9@648.27,782.17 ; v1(626,933) 647.43,933 CN1.12@648.27,932.17 ; v1(626,982) 648.1,982 CN1.13@648.27,982.17 ; v1(626,1133) 647.43,1133 CN1.16@648.27,1132.17 ; v1(626,1183) 647.43,1183 CN1.17@648.27,1182.17 ; v1(626,1334) 646.43,1334 CN1.20@648.27,1332.17 ; v1(626,1384) 646.43,1384 CN1.21@648.27,1382.17 ; v1(626,1584) 646.43,1584 CN1.25@648.27,1582.17 ; v1(626,1984) 646.43,1984 CN1.33@648.27,1982.17 ; v1(626,2134) 646.43,2134 CN1.36@648.27,2132.17 ; v1(626,2233) 647.43,2233 CN1.38@648.27,2232.17 ; v1(626,2331) 627.17,2332.17 CN1.40@648.27,2332.17 ; v1@637.57,402 v1(638,402) ; v1(644,1511) v1@644,1516 ; CN1.32@646.43,1934 CN1.32@648.27,1932.17 655,1925.43 655,1913 v1(660,1913) ; CN1.1@647.43,383 CN1.1@648.27,382.17 ; CN1.28@647.43,1733 CN1.28@648.27,1732.17 649.43,1731 v1(671,1731) ; v1(676,483) 697.43,483 CN1.43@698.27,482.17 ; v1(676,632) 698.1,632 CN1.46@698.27,632.17 ; v1(676,833) 697.43,833 CN1.50@698.27,832.17 ; v1(676,983) 697.43,983 CN1.53@698.27,982.17 ; v1(676,1132) 698.1,1132 CN1.56@698.27,1132.17 ; v1(676,1434) 696.43,1434 CN1.62@698.27,1432.17 ; v1(676,2283) 697.43,2283 CN1.79@698.27,2282.17 ; v1(677,431) 697.1,431 CN1.42@698.27,432.17 ; v1(677,681) 697.1,681 CN1.47@698.27,682.17 ; v1(677,1582) 677.17,1582.17 CN1.65@698.27,1582.17 ; v1(677,2182) 698.1,2182 CN1.77@698.27,2182.17 ; CN1.68@698.1,1732 699.1,1731 v1(721,1731) ; v1(826,381) 847.1,381 CN1.81@848.27,382.17 ; v1(826,534) 846.43,534 CN1.84@848.27,532.17 ; v1(826,584) 827.83,582.17 CN1.85@848.27,582.17 ; v1(826,882) 848.1,882 CN1.91@848.27,882.17 ; v1(826,1034) 846.43,1034 CN1.94@848.27,1032.17 ; v1(826,1183) 847.43,1183 CN1.97@848.27,1182.17 ; v1(826,1332) 848.1,1332 CN1.100@848.27,1332.17 ; v1(826,1480) 846.1,1480 CN1.103@848.27,1482.17 ; v1(826,1632) 848.1,1632 CN1.106@848.27,1632.17 ; v1(826,1780) 846.1,1780 CN1.109@848.27,1782.17 ; v1(826,1932) 848.1,1932 CN1.112@848.27,1932.17 ; v1(826,2083) 847.43,2083 CN1.115@848.27,2082.17 ; v1(826,2233) 847.43,2233 CN1.118@848.27,2232.17 ; v1(826,2335) 845.43,2335 CN1.120@848.27,2332.17 ; v1(828,722) 838.1,722 CN1.88@848.27,732.17 ; v1(876,434) 896.43,434 CN1.122@898.27,432.17 ; v1(876,483) 897.43,483 CN1.123@898.27,482.17 ; v1(876,634) 896.43,634 CN1.126@898.27,632.17 ; v1(876,934) 896.43,934 CN1.132@898.27,932.17 ; v1(876,1084) 896.43,1084 CN1.135@898.27,1082.17 ; v1(876,1235) 878.83,1232.17 CN1.138@898.27,1232.17 ; v1(876,1533) 876.83,1532.17 CN1.144@898.27,1532.17 ; v1(876,1832) 898.1,1832 CN1.150@898.27,1832.17 ; v1(876,1982) 876.17,1982.17 CN1.153@898.27,1982.17 ; v1(876,2283) 897.43,2283 CN1.159@898.27,2282.17 ; v1(877,782) 898.1,782 CN1.129@898.27,782.17 ; v1(877,1380) 896.1,1380 CN1.141@898.27,1382.17 ; v1(877,1681) 897.1,1681 CN1.147@898.27,1682.17 ; v1(877,2133) 897.43,2133 CN1.156@898.27,2132.17 ; C39.2@1300,305.5 1308.5,314 C36.2@1356,314 ; C108.2@1455.5,1323 C108.2@1455.56,1323 1472,1323 1489,1340 1489,1407.5 C110.2@1495.5,1414 ; C81.2@2410.5,780 2410.5,635.5 CN5.5@2395,620 2395,615 2438,572 C60.2@2478,572 ; v1(2464,1868) v1(2464,1890) ; v1(2465,529) v1(2465,551) 2465,552 2470,552 2470,569 C60.2@2475,569 ; C80.2@2471,767 2471.5,767 C61.2@2524,714.5 ; C188.2@2495,2052.5 C188.2@2496,2053.5 ; C59.2@2556,578 C59.2@2556,575 ; C191.2@2685,2064 2653.5,2032.5 2561.5,2032.5 2540.5,2053.5 C188.2@2496,2053.5 ; v1(2860,1800) 2864,1800 2884,1820 2884,1834 2904,1854 2940,1854 2978,1816 2978,1774.5 C197.2@2977.5,1774 ; v1(2464,1890) 2464,1912.97 CN13.5@2395,1981.97 2396.97,1981.97 2468.5,2053.5 C188.2@2496,2053.5 ; v1(2464,1890) 2469,1885 C192.2@2513,1885 ; C60.2@2475,569 C60.2@2476,570 ; C60.2@2475,569 2476,569 C60.2@2476,570 ; C60.2@2476,570 C60.2@2478,572 ; C60.2@2478,572 2511,539 2513,539 2515,537 2555,537 2555,574 C59.2@2556,574 ; C192.2@2513,1885 2539,1885 2541,1887 2552,1876 2553,1877 2553,1915 2552,1916 2552,1919 2521,1919 2518,1916 2514,1920 2513,1920 C192.2@2513,1885 ; C59.2@2556,574 2557,574 C59.2@2556,575 ; C59.2@2556,574 C59.2@2556,575
  Bottom Layer w16: C169.2@1113,1690 1113,1724 C159.2@1117,1728
  Bottom Layer w16.14: v1(1247,805) 1331,805 1333,803 1338,808 1342,804 1356,818 C45.2@1450,818
  Bottom Layer w17.72: C166.2@1202,1649.5 1249,1649.5 ; C165.2@1251,1689 1251,1651.5 1249,1649.5 ; 1290,1649 1289.5,1649.5 1249,1649.5 ; C168.2@1299,1669.5 1325.5,1669.5 C164.2@1346,1690 ; v1(2679,1802) 2680,1801 2680,1751 2688,1743 C200.2@2688,1705 ; v1(2710,161) v1(2733,161) ; C201.2@2788.5,1595 2772,1611.5 C199.2@2772,1644.44 2772,1644.5 2819,1644.5 ; C196.2@2819,1683 2819,1644.5 ; v1(2887,1609) 2887,1662 2886,1663 ; C195.2@2912,1685 2908,1681 2908,1663 2886,1663 ; C130.2@3002,1161 3002,1141 ; C129.2@3003,1277 3003,1307.5 3020.5,1325 3052,1356.5 3052,1362 v1@3062,1372 ; C135.2@3003.62,1107.41 3002,1108.97 3002,1141 ; v1(3022,1139) v1@3022,1141 ; v1(3043,1372) v1@3062,1372 ; v1(3044,1139) 3042,1141 v1@3022,1141 ; C134.2@3071,1464 3087.5,1447.5 3087.5,1397.5 3065,1375 v1@3062,1372 ; C118.2@3073,1315 3090,1332 v1(3090,1372) v1(3066,1372) 3065,1372 v1@3062,1372 ; 2819,1644.5 2845,1644.5 2865,1664.5 2866.5,1663 2886,1663 ; 3002,1141 v1@3022,1141
  Bottom Layer w18: v2@2744,641 2751,648 C63.2@2766,648 ; C137.2@2789.5,922 2789.5,877.5 2780,868 2795,868 v1(2801,862)
  Bottom Layer w19.29: v1(670,1781) 670,1732 v1(671,1731) CN1.68@697.1,1731 ; v1(1296,975) C103.2@1296,984.5 ; C37.2@1437,449 1437,473 v1(1439,475) v1(1461,475) 1482,475 v1(1483,474) ; C108.2@1455.5,1323 1480.5,1298 1505,1298 C86.2@1505,1307 ; C172.2@1477,2018.5 v1(1477,2039) v1(1498,2039) 1498,2048 v1(1510,2060) ; v1@1487,662 v1(1487,669) ; 1494,687 v1(1486,695) ; v1@1494,695 v1(1486,695) ; C110.2@1495.5,1414 1521,1388.5 v1(1521,1371) ; v1(1497,1371) v1(1521,1371) ; v1@1511,664 v1@1512,665 ; v1(1512,694) v1@1512,665 ; v1(1513,670) v1@1513,666 ; v1(2055,174) 2080,149 C47.2@2080,75 ; v1(2465,1211) v1(2465,1233) 2509,1233 C127.2@2517,1241 ; 2548,42 v1@2586,42 ; v1(2612,40) v1@2612,42 ; v1(2638,40) 2636,42 v1@2612,42 ; v3(2683,1142) 2683,1093 2684,1093 2700,1077 C141.2@2700,1054 ; v1@2692,349 v1(2693,349) ; v2@2736,462 2808,462 v2@2809,461 ; v1(2762,278) 2772,288 2772,291 ; C137.2@2789.5,922 2822.5,955 2822.5,954.5 v1(2827,950) 2835.5,941.5 2838.5,941.5 ; C133.2@2830,1466 v1(2830,1499) ; 2837,940 2838.5,941.5 ; v1(2849,923) 2849,931 2838.5,941.5 ; v1(2859,167) 2859,223 ; v1@2901,303 2904,300 2905.5,298.5 v1(2907,297) 2907,299 2907,309 ; C67.2@2993,479 2993,477 v1(3011,459) ; C79.2@2999,601 3016,601 3016,595 3017,595 v1(3021,591) 3035,605 3035,613 v1(3036,614) 3035,615 3035,631.5 C76.2@3020.5,646 ; C77.2@3068,781 3066,783 v1(3066,808) v1(3090,808) ; R56.1@3470,313 3463,306 v1(3463,277) v1(3487,277) ; 3836,736 3870,736 v1(3984,736) ; 3878,52 v1(3983,52) ; 3960,53 v1@3982,53 ; 3960,757 v1@3983,757 ; 3961,75 v1@3982,75 ; CN11.5@3975,1310 v1@3975,1407 ; v1(4022,1407) v1(3998,1407) v1(3976,1407) v1@3975,1407 ; v1(4022.5,1428.5) 4022,1429 v1(3998,1429) v1(3975,1429) v1@3975,1407 ; v1(4027.5,51.5) v1@4027,52 ; v1(4030.5,759) v1@4029.5,758 ; v1(4032,735) v1@4031,736 ; v1(1486,695) 1486,670 v1(1487,669) ; v1(1487,669) 1493,669 1494,668 1505,668 1512,661 1513,662 v1@1513,666 ; v1(1496,1346) 1505,1337 C86.2@1505,1316 ; v1(1496,1346) 1496,1307 C86.2@1505,1307 ; v1(1496,1346) v1(1523,1346) ; C86.2@1505,1307 C86.2@1505,1316 ; C86.2@1505,1316 1523,1316 v1(1523,1346) ; v1@1512,665 v1@1513,666 ; v1(1521,1371) 1521,1348 v1(1523,1346) ; v1@2586,42 v1@2588,42 ; v1@2586,42 v1(2588,40) v1@2588,42 ; v1@2588,42 v1@2612,42 ; v1@3982,53 v1@3983,53 ; v1@3982,53 v1(3983,52) ; v1@3982,53 v1(3982,74) v1@3982,75 ; v1@3982,75 v1(4005,75) ; v1(3983,52) v1@3983,53 ; v1(3983,52) v1(4005,52) ; v1@3983,53 v1@4005,53 ; v1@3983,757 v1@4006,757 ; v1@3983,757 3983,737 v1(3984,736) ; v1@3983,757 v1(3983,758) v1@4005,758 ; v1(3984,736) v1(4006,736) ; v1(4005,52) v1@4027,52 ; v1(4005,52) v1@4005,53 ; v1@4005,53 v1@4006,53 ; v1@4005,53 v1(4005,75) ; v1(4005,75) 4027,75 v1(4027.5,74.5) v1@4006,53 ; v1@4005,758 v1@4006,758 ; v1@4005,758 v1(4006,759) v1@4006,758 ; v1@4006,53 4026,53 v1@4027,52 ; v1(4006,736) v1@4031,736 ; v1(4006,736) v1@4006,757 ; v1@4006,757 v1@4010,757 ; v1@4006,757 v1@4006,758 ; v1@4006,758 v1@4029.5,758 ; v1@4010,757 v1@4031,736 ; v1@4010,757 4028.5,757 v1@4029.5,758
  Bottom Layer w19.68: CN1.68@697.1,1731 698.1,1732 CN1.68@698.27,1732.17 ; C104.2@1204,984.5 1232.5,984.5 1252,1004 1271.5,984.5 1296,984.5 1334.5,984.5 C101.2@1354,1004 ; C44.2@1434,593 1454.5,613.5 1454.5,639 C43.2@1454.56,639 1466,639 1494,667 1494,668 1494,687 1494,695 1494,726.5 C46.2@1501.5,734 ; C172.2@1477,2018.5 1462.5,2004 1485.5,1981 1510,1981 v1(1510,2060) 1510,2087.5 1521.5,2099 1512,2108.5 C173.2@1512,2147 ; CN13.4@2395,1781.97 C146.2@2395,1662 ; C146.2@2402,1655 C146.2@2395,1662 ; C147.2@2456,1673.5 2406.5,1673.5 C146.2@2395,1662 ; C115.2@3944,993 C113.2@3993.5,993 ; CN11.4@3983,1102 3983,1003.5 C113.2@3993.5,993 ; C113.2@3998,988.5 C113.2@3993.5,993
  Bottom Layer w20: C102.2@1425.5,1094 1436,1104.5 C100.2@1436,1140 ; C38.2@1431.5,401 1437,406.5 C37.2@1437,449 ; R80.1@1865,1019 1916.11,1070.11 CN10.7@1916.11,1073.89 ; R128.1@1866,1687 1887,1687 1895,1695 ; R28.1@1869,682 CN6.8@1916.11,634.89 ; R29.1@1878,324 1916.11,362.11 CN6.7@1916.11,391.89 ; R127.1@1879,2047 1902,2047 ; R79.1@1894,1376 1916.11,1353.89 ; CN6.8@1916.11,628.11 1954,666 1954,673 1959,678 C107.2@1959,738 ; CN10.8@1916.11,1310.11 1956,1310.11 1987.11,1279 C171.2@2014,1279 ; CN9.4@2395,1102 2420,1077 2420,975 2426.5,981.5 2491,981.5 2502.5,993 2548,993 2574,1019 2574,1062 2533.5,1102.5 C143.2@2515,1102.5 ; CN9.5@2395,1302 2395,1440.5 2399.5,1445 2412.5,1432 2446,1432 2465.5,1412.5 C140.2@2520,1412.5 ; CN5.4@2404,411 2404,302 2416.5,314.5 C19.2@2459,314.5 ; C81.2@2410.5,780 2423.5,767 C80.2@2471,767 ; C16.2@2468.5,96 2469,95.5 2469,83 ; C127.2@2517,1241 2517,1260 ; C132.2@2517,1277 2517,1260 ; C142.2@2554,1205 2554,1258 2555,1259 2554,1260 2517,1260 ; C62.2@2692,373 2692,349 2692,328 C73.2@2693,327 ; C126.2@2732,1463 2738,1457 2839,1457 C133.2@2830,1466 ; 2772,291 2779.5,298.5 2824,298.5 ; C71.2@2776,309.5 2813,309.5 ; C69.2@2827,314 2822.5,309.5 2813,309.5 ; 2859,223 2879.5,243.5 2879.5,258.5 2878,260 C70.2@2878,298.44 C70.2@2878,298.5 ; C68.2@2924,316 2914,316 2912,314 2907,309 2904,306 2901,303 2896.5,298.5 C70.2@2878,298.5 ; C182.2@3079,1964 3079,2024 ; R104.1@3442,1001 CN12.7@3502.11,1061.11 ; R151.1@3454,2055 CN16.8@3497.72,2011.28 ; R55.1@3460,701 3502.11,658.89 CN8.8@3502.11,628.11 ; R56.1@3470,313 3470,359.78 CN8.7@3502.11,391.89 ; R103.1@3472,1381 3502.11,1350.89 ; R152.1@3475,1685 3497.72,1707.72 ; CN11.2@3783,1302 3819,1338 C177.2@3819,1441.44 3819,1441.5 3861.5,1441.5 C176.2@3866,1437 ; 3870,736 C112.2@3870,772 ; C50.2@3935,316 3981.5,316 C51.2@3983,314.5 ; C178.2@3945,1663 3965.5,1683.5 3999,1683.5 4001,1685.5 4001,1731 3983.54,1748.46 CN15.4@3983.54,1780 ; CN11.5@3975,1310 CN11.5@3983,1302 ; CN7.4@3983,420 C51.2@3983,314.5 ; C51.2@3985,312.5 C51.2@3983,314.5 ; 2813,309.5 2824,298.5 ; 2824,298.5 C70.2@2878,298.5 ; 3819,62 3829,52 3878,52 3869,61 3869,101 3865.5,104.5 3819,104.5 C49.2@3819,104.44 3819,62
  Bottom Layer w22: CN10.8@1916.11,1310.11 1916.11,1353.89
  Bottom Layer w22.05: C114.2@3824,774.5 C114.2@3824,774.44 3824,748 3836,736
  Bottom Layer w23: 1902,2047 1916.38,2032.62 CN14.8@1916.38,1990.24 ; CN6.8@1916.11,628.11 CN6.8@1916.11,634.89 ; 2469,83 2507,83 2548,42
  Bottom Layer w24: CN5.4@2395,420 CN5.4@2404,411 ; C17.2@2423.5,78 2427.5,74 2460,74 2469,83 ; 3497.72,1707.72 CN16.7@3497.72,1753.99 ; CN16.8@3497.72,1990.21 CN16.8@3497.72,2011.28
  Bottom Layer w25: C43.2@1454.5,639 1484.5,609 C22.2@1494,618.5 ; v1@1494,667 C22.2@1494,618.5 ; 1895,1695 1895,1732.64 CN14.7@1916.38,1754.02 ; CN12.7@3502.11,1061.11 CN12.7@3502.11,1073.89 ; C22.2@1494,618.5 1499.5,624 1501,624 1494,617 C22.2@1494,618.5
  Bottom Layer w30: C7.2@1387.25,2237.89 1469.93,2237.89 1536.9,2237.89 C9.2@1542.36,2232.36 ; CN12.8@3502.11,1310.11 3502.11,1350.89
  other v1: 2015,173 2094,174 2014,254 2090,254 2054,255 1989,818 2070,818 2070,897 1991,898 2033,899 2008,1519 2052,1519 2090,1519 2007,1600 2091,1600 1650,2206 1579,2230 1603,2230 1627,2230 1650,2230 1578,2252 1602,2252 1626,2252 1343,2468 1367,2468 1390,2468 328,2475 1319,2492 1343,2492 1367,2492 1390,2492 663,2509 1342,2514 1366,2514 1389,2514 639,2525 1320,2537 1344,2537 1368,2537 1391,2537 1391,2561 1319,2583 1343,2583 1367,2583 1390,2583 1196,2631 1220,2631 1244,2631 1267,2631 1100,2632 1124,2632 1148,2632 1171,2632 1195,2653 1219,2653 1243,2653 1266,2653 1099,2654 1123,2654 1147,2654 1170,2654
  other v2: 1162.54,457.42 1225.46,457.42 2738.54,460.42 2801.46,460.42 1103.42,516.54 1162.54,516.54 1225.46,516.54 1284.58,516.54 2679.42,519.54 2738.54,519.54 2801.46,519.54 2860.58,519.54 1103.42,579.46 1162.54,579.46 1225.46,579.46 1284.58,579.46 2679.42,582.46 2738.54,582.46 2801.46,582.46 2860.58,582.46 1162.54,638.58 1225.46,638.58 2738.54,641.58 2801.46,641.58 1162.54,1139.42 1225.46,1139.42 2738.54,1142.42 2801.46,1142.42 1103.42,1198.54 1162.54,1198.54 1225.46,1198.54 1284.58,1198.54 2679.42,1201.54 2738.54,1201.54 2801.46,1201.54 2860.58,1201.54 1103.42,1261.46 1162.54,1261.46 1225.46,1261.46 1284.58,1261.46 2679.42,1264.46 2738.54,1264.46 2801.46,1264.46 2860.58,1264.46 1162.54,1320.58 1225.46,1320.58 2738.54,1323.58 2801.46,1323.58 2737.54,1799.94 2800.46,1799.94 1158.54,1818.94 1221.46,1818.94 2678.42,1859.07 2737.54,1859.07 2800.46,1859.07 2859.58,1859.07 1099.42,1878.07 1158.54,1878.07 1221.46,1878.07 1280.58,1878.07 2678.42,1921.98 2737.54,1921.98 2800.46,1921.98 2859.58,1921.98 1099.42,1940.98 1158.54,1940.98 1221.46,1940.98 1280.58,1940.98 2737.54,1981.11 2800.46,1981.11 1158.54,2000.11 1221.46,2000.11 3884.16,2516.2 3553.16,2517.2 3856.6,2535.88 3911.72,2535.88 3525.6,2536.88 3580.72,2536.88 3884.16,2555.57 3553.16,2556.57
FMC_GA0: CN1.34 R5.1 | length 849.5
  Top Layer w5: v1(257,2577) 278.12,2577 R5.1@278.27,2576.85
  MidLayer1 w5: v1(257,2577) 276,2558 322,2558 483,2397 483,2048 507,2024 606,2024 614,2032 v1(624,2032)
  Bottom Layer w5: v1(624,2032) 626,2032 626.17,2032.17 CN1.34@648.27,2032.17
FMC_GA1: CN1.75 R6.2 | length 942.8
  Top Layer w5: v1(254,2535) 272.87,2535 R6.2@278.27,2529.61
  MidLayer1 w5: v1(254,2535) 330,2535 473,2392 473,2043 502,2014 646,2014 676,2044 v1(676,2083)
  Bottom Layer w6: v1(676,2083) 676.83,2082.17 CN1.75@698.27,2082.17
GPIO0_CAM1: R31.2 R33.1 U1.18 | length 929.3
  Top Layer w5: R33.1@1144,296 1144,265 1160,265 1160,264 1164,264 1208,220 1384,220 1436,168 1578,168 1593,153 1817,153 1833,137 1914,137 1941.79,164.79 U1.18@1977.23,164.79
GPIO0_CAM2: R171.1 R172.2 U1.3 | length 759.3
  Top Layer w5: U1.3@2130.77,204.16 2134.93,200 2153,200 2178,175 2179,175 v1(2179,177) ; R172.2@2656,270 R172.2@2656,278 ; R172.2@2659,278 R172.2@2657,278 ; R172.2@2656,278 v1@2656,292 ; R172.2@2656,278 R172.2@2657,278 ; v1@2656,292 v1(2657,292) ; v1@2656,292 2656,312 2657,313 v1(2657,292) ; R172.2@2657,278 v1(2657,292)
  MidLayer1 w5: v1(2179,177) 2188,177 2215,204 2255,204 2315,144 2533,144 2573,184 2573,201 2582,210 2625,210 2638.5,223.5 2638.5,273.5 v1(2657,292)
GPIO0_CAM3: R174.1 R175.2 U4.18 | length 908.1
  Top Layer w5: R175.2@1144.72,941.34 1158.66,941.34 1207,893 1404,893 1437,860 1711,860 1752,819 1801,819 1819,801 1892,801 1900.13,809.13 U4.18@1953.78,809.13
  Top Layer w10: R174.1@1142.76,978.11 1142.76,943.31 R175.2@1144.72,941.34
GPIO0_CAM4: R177.1 R178.2 U4.3 | length 943.2
  Top Layer w5: U4.3@2107.32,848.5 2135.5,848.5 2147,837 v1(2147,834) ; R178.2@2656,949 2656,973 v1@2693,973 ; R177.1@2658,996 2657,995 2671,995 v1@2693,973 ; v1(2700,972) 2699,973 v1@2693,973
  MidLayer1 w5: v1(2147,834) 2162,849 2162,873 2170,881 2190,881 2206.5,897.5 2238,897.5 2296.5,839 2433,839 2467,805 2580,805 2594,819 2645,819 2700.5,874.5 2700.5,900.5 2716,916 2716,952 2717,953 2696,974 2698,974 v1(2700,972)
GPIO0_CAM5: R180.1 R181.2 U5.18 | length 958.7
  Top Layer w5: R180.1@1128.98,1659.21 1128.98,1625.02 1130,1624 1141,1624 1181,1584 1194,1584 1206.5,1571.5 1387.5,1571.5 1399,1560 1409,1560 1446,1523 1708,1523 1730,1501 1817,1501 1846,1472 1914,1472 1929,1487 1929,1492 1946.92,1509.92 U5.18@1971.5,1509.92
GPIO0_CAM6: R183.1 R184.2 U5.3 | length 699.4
  Top Layer w5: U5.3@2125.04,1549.29 2152.71,1549.29 v1(2153,1549) ; v1(2652,1661) 2688,1661 R184.2@2690,1663 ; R184.2@2690,1653 R184.2@2690,1663 ; R183.1@2690,1683 R184.2@2690,1663
  MidLayer1 w5: v1(2153,1549) 2153,1559 2188,1594 2595,1594 2613,1576 2629,1576 2639,1586 2639,1623 2645,1629 2645,1654 v1(2652,1661)
MODE1_CAM1: R45.1 U1.15 | length 84.7
  Top Layer w5: R45.1@1898,237 1914,237 1927.16,223.84 U1.15@1977.23,223.84
MODE1_CAM2: R71.1 U1.24 | length 146.2
  Top Layer w5: U1.24@2103.21,137.23 2134.77,137.23 2144,128 2144,68 2172,40 R71.1@2174,40
MODE1_CAM3: R95.1 U4.15 | length 92.5
  Top Layer w5: R95.1@1874,899 1887,899 1917.81,868.19 U4.15@1953.78,868.19
MODE1_CAM4: R119.1 U4.24 | length 113.4
  Top Layer w5: U4.24@2079.76,781.57 2116.43,781.57 2165,733 R119.1@2173,733
MODE1_CAM5: R143.1 U5.15 | length 70.2
  Top Layer w5: R143.1@1902.91,1572.91 1906.85,1568.98 U5.15@1971.5,1568.98
MODE1_CAM6: R167.1 U5.24 | length 111
  Top Layer w5: U5.24@2097.48,1482.36 2097.48,1471.52 2110,1459 2143,1459 R167.1@2178,1424
MODE2_CAM1: R48.1 U1.16 | length 82.2
  Top Layer w5: R48.1@1898,197 1905.16,204.16 U1.16@1977.23,204.16
MODE2_CAM2: R72.1 U1.1 | length 110.1
  Top Layer w5: U1.1@2130.77,164.79 2137,158.56 2137,153 2155,135 2155,87 2162,80 2173,80 R72.1@2174,79
MODE2_CAM3: R96.1 U4.16 | length 84.5
  Top Layer w5: R96.1@1874,860 1885.5,848.5 U4.16@1953.78,848.5
MODE2_CAM4: R120.1 U4.1 | length 80.2
  Top Layer w5: U4.1@2107.32,809.13 2142.46,774 R120.1@2173,774
MODE2_CAM5: R144.1 U5.16 | length 75.1
  Top Layer w5: R144.1@1902.91,1533.54 1918.66,1549.29 U5.16@1971.5,1549.29
MODE2_CAM6: R168.1 U5.1 | length 87.8
  Top Layer w5: U5.1@2125.04,1509.92 2147.08,1509.92 2156,1501 2156,1474 2166,1464 R168.1@2178,1464
MODE3_CAM1: R49.1 U1.17 | length 90.6
  Top Layer w5: R49.1@1898,157 1902,157 1929.47,184.47 U1.17@1977.23,184.47
MODE3_CAM2: R73.1 U1.2 | length 95.8
  Top Layer w5: U1.2@2130.77,184.47 2149.53,184.47 2159,175 2159,149 2175,133 R73.1@2175,118
MODE3_CAM3: R97.1 U4.17 | length 82.6
  Top Layer w5: R97.1@1874,822 1880.82,828.82 U4.17@1953.78,828.82
MODE3_CAM4: R121.1 U4.2 | length 71.8
  Top Layer w5: U4.2@2107.32,828.82 2125,828.82 2139.82,814 R121.1@2173,814
MODE3_CAM5: R145.1 U5.17 | length 93.2
  Top Layer w5: R145.1@1902.91,1494.17 1911.17,1494.17 1926,1509 1926,1526 1929.61,1529.61 U5.17@1971.5,1529.61
MODE3_CAM6: R169.1 U5.2 | length 64.4
  Top Layer w5: U5.2@2125.04,1529.61 2150.39,1529.61 R169.1@2178,1502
